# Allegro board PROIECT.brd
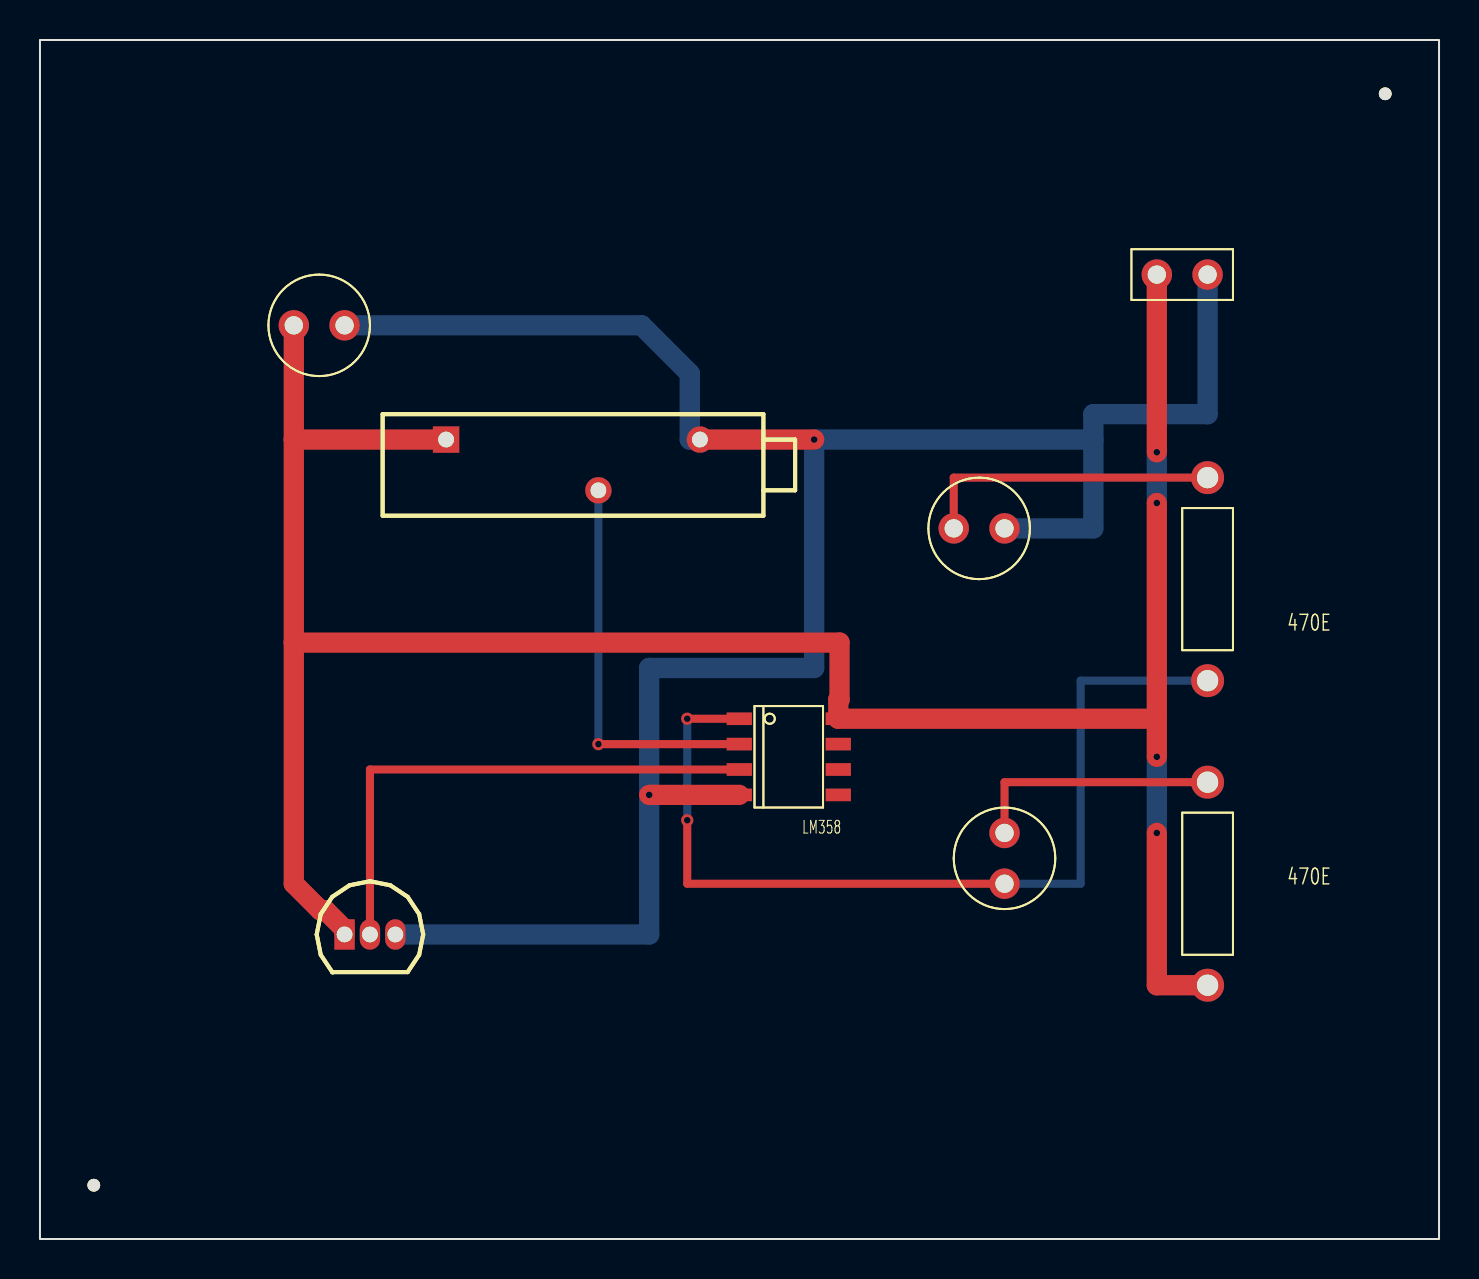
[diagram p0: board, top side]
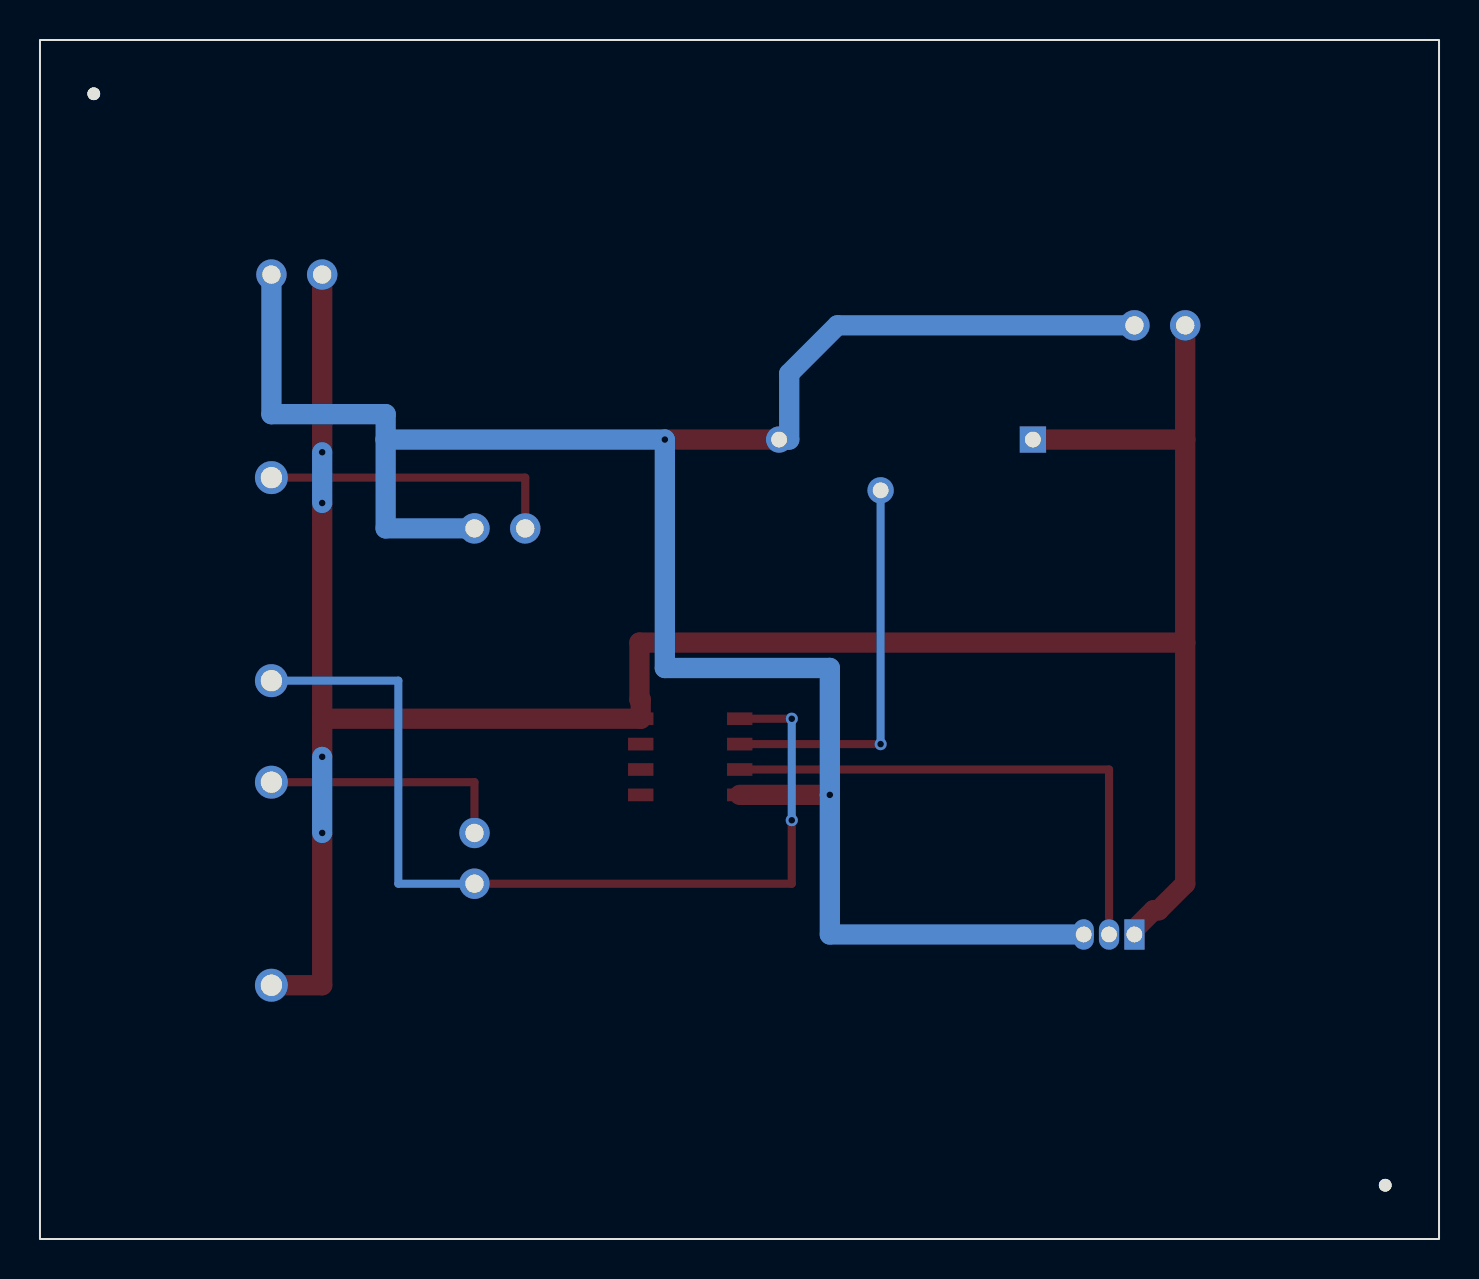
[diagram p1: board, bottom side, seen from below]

Outline 70 x 60 mm; copper layers: TOP, BOTTOM. Coordinates in mm from the lower left corner of the outline.
Outline path: rectangle 0,0 70,60

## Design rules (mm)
nets with their own width: min track width 0.406; nets N00529 N00677 N00684 N00778 N03337
nets with their own width: min track width 1.016; nets +5V GND

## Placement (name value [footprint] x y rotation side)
C1  100uF  [CAP196]  12.7 45.72 270 top
IC1  LM35  [TO92]  15.24 15.24 0 top
J1  CON2  [JUMPER2]  55.88 48.26 0 top
LED1  RED LED  [CAP196]  48.26 20.32 180 top
LED2  GREEN LED  [CAP196]  45.72 35.56 270 top
NOREF  -  [unnamed]  2.69 2.69 0 top
NOREF#2  -  [unnamed]  67.31 57.31 0 top
R1  470E  [RES400]  58.42 12.7 0 top
R2  470E  [RES400]  58.42 27.94 0 top
U1G1  LM358  [SOIC8]  37.47 24.13 0 top
VR1  10k  [VRES9]  20.32 40.01 180 top

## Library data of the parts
C1 = CAP POL
IC1 = LM35/SO_10
J1 = CON2
LED1 LED2 = LED
R1 R2 = R
U1G1 = LM358
VR1 = POT

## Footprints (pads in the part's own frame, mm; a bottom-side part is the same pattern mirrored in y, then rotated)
CAP196
  round 1.524 hole 0.914: 1(0,0) 2(0,2.54)
JUMPER2
  round 1.524 hole 0.914: 1(0,0) 2(2.54,0)
RES400
  round 1.651 hole 1.067: 1(0,0) 2(0,10.16)
SOIC8
  rect 1.27x0.635 smd: 1(-2.477,1.905) 2(-2.477,0.635) 3(-2.477,-0.635) 4(-2.477,-1.905) 5(2.477,-1.905) 6(2.477,-0.635) 7(2.477,0.635) 8(2.477,1.905)
TO92
  rect 1.016x1.524 hole 0.787: 1(0,0)
  oval 1.016x1.524 hole 0.787: 2(1.27,0) 3(2.54,0)
unnamed
  round 0.635 hole 3.175 unplated: (0,0)
VRES9
  rect 1.321x1.321 hole 0.787: 1(0,0)
  round 1.321 hole 0.787: 2(-7.62,2.54) 3(-12.7,0)

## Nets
+5V: C1.1 IC1.1 J1.1 R1.1 U1G1.8 VR1.1
GND: C1.2 IC1.3 J1.2 LED2.2(CATHODE) U1G1.4 VR1.3
N00529: LED2.1 R2.2
N00677: U1G1.2 VR1.2(WIPER)
N00684: IC1.2(VO) U1G1.3
N00778: LED1.2(CATHODE) R2.1 U1G1.1
N03337: LED1.1 R1.2

Pads without a net: U1G1 5 6 7

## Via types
v1: diameter 0.61, hole 0.33, TOP to BOTTOM, 9 vias

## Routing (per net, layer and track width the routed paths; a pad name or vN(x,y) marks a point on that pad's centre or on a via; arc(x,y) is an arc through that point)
+5V: length 124.5
  TOP w1.016: 12.7,29.84 40.01,29.84 40.01,26.99 39.94,26.99 U1G1.8 55.88,26.04 ; 12.7,29.84 12.7,40.01 ; 12.7,29.84 12.7,17.78 14.03,16.45 14.28,16.45 15.24,15.49 IC1.1 ; 12.7,40.01 VR1.1 ; 12.7,40.01 C1.1 ; v1(55.88,24.13) 55.88,26.04 ; 55.88,26.04 v1(55.88,36.83) ; v1(55.88,20.32) 55.88,12.7 R1.1 ; J1.1 v1(55.88,39.37)
  BOTTOM w1.016: v1(55.88,39.37) v1(55.88,36.83) ; v1(55.88,24.13) v1(55.88,20.32)
GND: length 114.9
  TOP w1.016: U1G1.4 v1(30.48,22.23) ; v1(38.73,40.01) VR1.3
  BOTTOM w1.016: 52.7,40.01 52.7,35.56 LED2.2 ; 52.7,40.01 52.7,41.27 58.42,41.27 J1.2 ; 52.7,40.01 v1(38.73,40.01) 38.73,28.57 30.48,28.57 v1(30.48,22.23) 30.48,15.24 IC1.3 ; C1.2 30.1,45.72 32.51,43.31 32.51,40.01 VR1.3
N00529: length 15.2
  TOP w0.406: LED2.1 45.72,38.1 R2.2
N00677: length 19.7
  TOP w0.406: v1(27.94,24.77) U1G1.2
  BOTTOM w0.406: v1(27.94,24.77) VR1.2
N00684: length 26.7
  TOP w0.406: 34.99,23.5 16.51,23.5 IC1.2
N00778: length 47.1
  TOP w0.406: U1G1.1 v1(32.38,26.04) ; LED1.2 32.38,17.78 v1(32.38,20.95)
  BOTTOM w0.406: LED1.2 52.07,17.78 52.07,27.94 R2.1 ; v1(32.38,26.04) v1(32.38,20.95)
N03337: length 12.7
  TOP w0.406: LED1.1 48.26,22.86 R1.2

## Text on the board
XSECTION_CHART: *  SURFACE - AIR | L1 TOP CONDUCTOR - COPPER | *  DIELECTRIC - FR-4 | L2 BOTTOM CONDUCTOR - COPPER | DESIGN CROSS SECTION CHART | ___________________________ | TOTAL THICKNESS 10.4 MIL | 1-2
COMPVAL_TYPE_TOP: FIGURE | FINISHED_SIZE | 13.0 | 31.0 | 36.0 | 42.0 | 125.0 | DRILL CHART: TOP to BOTTOM | ALL UNITS ARE IN MILS | PLATED | NON-PLATED | QTY | 9 | 6 | 8 | 4 | 2
